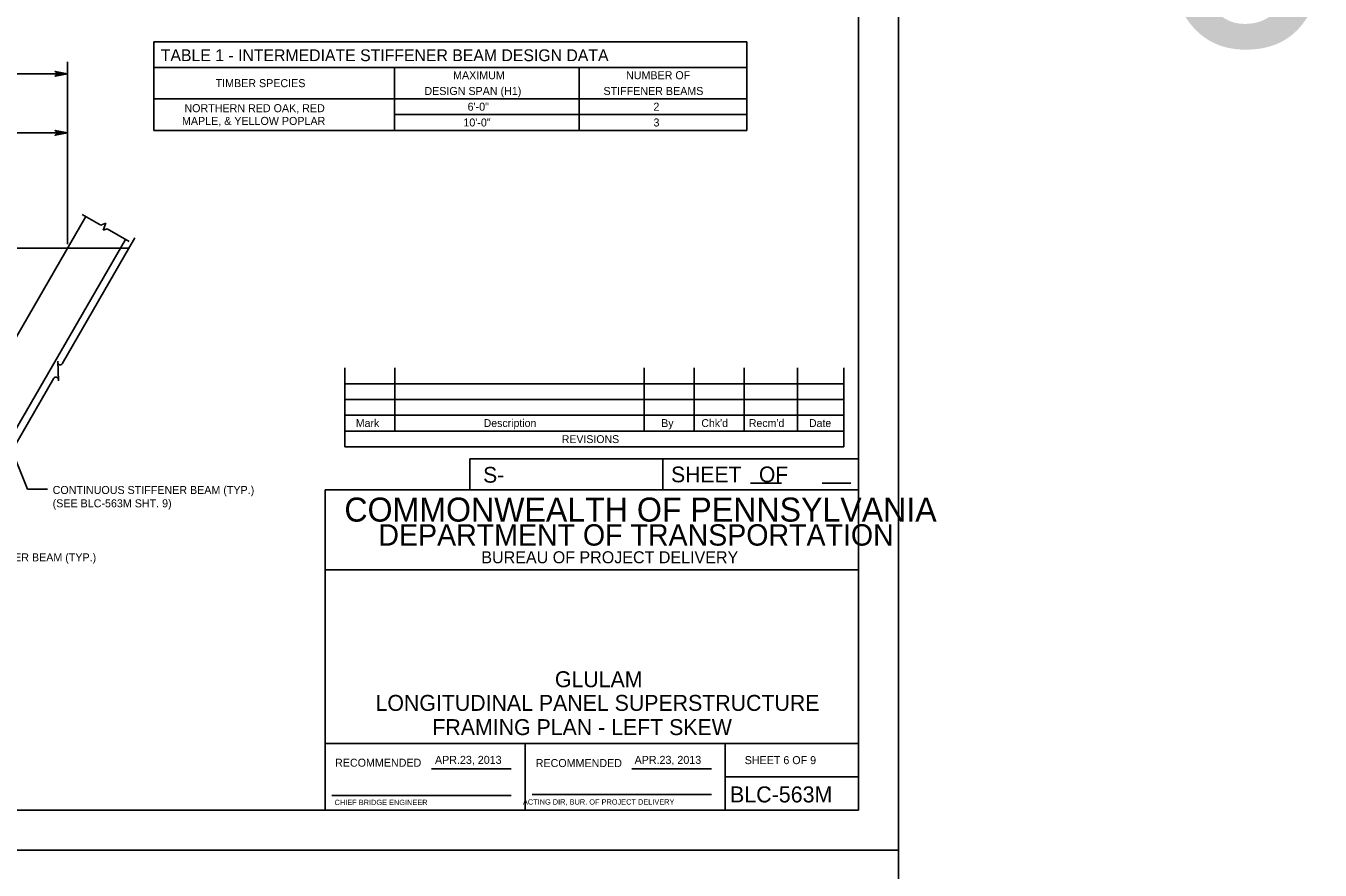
# Model space of a CAD drawing. Extents: x 638268 to 640277, y 295465 to 298435.
# Drawn here: x 639790.3 to 640275.4, y 297834 to 298150.4 of the extents above; entities that cross this region are included whole.
import ezdxf

# ---------------------------------------------------------------- set-up
doc = ezdxf.new("R2010")
doc.units = 0
for name, color, linetype in [('1', 7, 'Continuous'), ('2', 7, 'Continuous'), ('3', 7, 'Continuous'), ('4', 7, 'Continuous'), ('53', 7, 'Continuous'), ('8', 7, 'Continuous'), ('PLT-BNDY', 7, 'Continuous')]:
    doc.layers.add(name, color=color, linetype=linetype)

msp = doc.modelspace()

# ---------------------------------------------------------------- linework, layer by layer
at = {"layer": '2'}
for p, q in [((640102.46, 298420.46), (640102.46, 297856.46)), ((639646.92, 298067.04), (639828.98, 298067.04)), ((639909.92, 298022.15), (639909.92, 297992.62)), ((639928.62, 298022.15), (639928.62, 297998.53)), ((640022.13, 298022.15), (640022.13, 297998.53)), ((640040.83, 298022.15), (640040.83, 297998.53)), ((640059.53, 298022.15), (640059.53, 297998.53)), ((640079.59, 298022.15), (640079.59, 297998.53)), ((640096.94, 298022.15), (640096.94, 297992.62)), ((640096.94, 298016.24), (639909.92, 298016.24)), ((640096.94, 298010.34), (639909.92, 298010.34)), ((640096.94, 298004.43), (639909.92, 298004.43)), ((640096.94, 297998.53), (639909.92, 297998.53)), ((640096.94, 297992.62), (639909.92, 297992.62)), ((640102.46, 297988.11), (639956.78, 297988.11)), ((639956.78, 297988.11), (639956.78, 297976.46)), ((640029.09, 297988.11), (640029.09, 297976.46)), ((640102.46, 297988.11), (640102.46, 297976.46)), ((640061.95, 297979), (640073.6, 297979)), ((640088.83, 297979), (640099.56, 297979)), ((640102.46, 297976.46), (639902.46, 297976.46)), ((639902.46, 297976.46), (639902.46, 297856.46)), ((640102.46, 297976.46), (639956.78, 297976.46)), ((640102.46, 297946.46), (639902.46, 297946.46)), ((640102.46, 297881.46), (639902.46, 297881.46)), ((639977.46, 297856.46), (639977.46, 297881.46)), ((640052.46, 297881.46), (640052.46, 297856.46)), ((639942.42, 297871.96), (639972.19, 297871.96)), ((640017.42, 297871.96), (640047.33, 297871.96)), ((640052.46, 297868.96), (640102.46, 297868.96)), ((639904.96, 297861.96), (639972.19, 297861.96)), ((639980.08, 297862.33), (640047.33, 297862.33)), ((640102.46, 297856.46), (639316.46, 297856.46))]:
    msp.add_line(p, q, dxfattribs=at)
at = {"layer": '3'}
for p, q in [((639812.83, 298078.94), (639754.24, 297977.59)), ((639818.49, 298075.67), (639811.48, 298079.73)), ((639820.29, 298076.41), (639818.49, 298075.67)), ((639819.28, 298073.81), (639820.29, 298076.41)), ((639820.83, 298074.32), (639819.28, 298073.81)), ((639828.99, 298069.6), (639820.83, 298074.32)), ((639769.07, 297969.02), (639827.65, 298070.37)), ((639831.23, 298070.93), (639803.96, 298023.76)), ((639802.25, 298024.67), (639802.52, 298017.4)), ((639800.85, 298018.38), (639776.26, 297975.83))]:
    msp.add_line(p, q, dxfattribs=at)
for centre, start, end in [((639803.18, 298024.22), 179.9708, 329.9708), ((639801.6, 298017.86), 2.1036, 144.6422)]:
    msp.add_arc(centre, 0.909, start, end, dxfattribs=at)
at = {"layer": '4'}
for p, q in [((639805.95, 298068.61), (639805.95, 298136.91)), ((639805.95, 298132.41), (639672.04, 298132.41)), ((639805.95, 298068.61), (639805.95, 298114.76)), ((639764.31, 298110.26), (639805.95, 298110.26)), ((639790.99, 297976.71), (639798.48, 297976.71))]:
    msp.add_line(p, q, dxfattribs=at)
for points in [[(639805.95, 298132.41), (639801.29, 298131.53), (639801.65, 298131.78), (639801.83, 298132.09), (639801.89, 298132.41), (639801.83, 298132.72), (639801.65, 298133.03), (639801.29, 298133.28), (639805.95, 298132.41), (639801.65, 298133.03), (639801.83, 298132.72), (639805.95, 298132.41), (639801.89, 298132.41), (639801.83, 298132.09), (639805.95, 298132.41), (639801.65, 298131.78)], [(639805.95, 298110.26), (639801.29, 298109.38), (639801.65, 298109.63), (639801.83, 298109.94), (639801.89, 298110.26), (639801.83, 298110.57), (639801.65, 298110.88), (639801.29, 298111.13), (639805.95, 298110.26), (639801.65, 298110.88), (639801.83, 298110.57), (639805.95, 298110.26), (639801.89, 298110.26), (639801.83, 298109.94), (639805.95, 298110.26), (639801.65, 298109.63)], [(639783.76, 297994.44), (639790.99, 297976.71)]]:
    msp.add_lwpolyline(points, dxfattribs=at)
for points in [[(639802.95, 298132.91), (639802.95, 298131.91), (639805.95, 298132.41)], [(639802.95, 298110.76), (639802.95, 298109.76), (639805.95, 298110.26)]]:
    msp.add_lwpolyline(points, close=True, dxfattribs=at)
at = {"layer": '8'}
for p, q in [((639838.32, 298144.36), (640060.52, 298144.36)), ((639838.32, 298144.36), (639838.32, 298111.19)), ((640060.52, 298144.36), (640060.52, 298111.19)), ((639838.32, 298134.82), (640060.52, 298134.82)), ((639928.52, 298134.82), (639928.52, 298111.19)), ((639997.74, 298134.82), (639997.74, 298111.19)), ((639838.32, 298123.01), (640060.52, 298123.01)), ((639928.52, 298117.1), (640060.52, 298117.1)), ((639838.32, 298111.19), (640060.52, 298111.19))]:
    msp.add_line(p, q, dxfattribs=at)
at = {"layer": 'PLT-BNDY'}
for points in [[(639276.46, 298435.46), (640117.46, 298435.46), (640117.46, 297841.46), (639276.46, 297841.46)], [(639276.46, 297841.46), (640117.46, 297841.46), (640117.46, 297247.46), (639276.46, 297247.46)]]:
    msp.add_lwpolyline(points, close=True, dxfattribs=at)

# ---------------------------------------------------------------- texts
at = {"layer": '1'}
msp.add_text('SHEET 6 OF 9', height=3, dxfattribs=at).set_placement((640059.77, 297873.68))
at = {"layer": '2'}
for s, height, p in [('Mark', 2.952, (639914.02, 298000.03)), ('Description', 2.9523, (639961.92, 298000.03)), ('By', 2.952, (640028.49, 298000.03)), ("Chk'd", 2.952, (640043.52, 298000.03)), ("Recm'd", 2.953, (640061.33, 298000.03)), ('Date', 2.952, (640083.86, 298000.03)), ('REVISIONS', 2.952, (639991.2, 297994.01)), ('S-', 5.905, (639961.73, 297979.17)), ('COMMONWEALTH OF PENNSYLVANIA', 9, (639909.71, 297964.58)), ('DEPARTMENT OF TRANSPORTATION', 8.0002, (639922.46, 297955.58)), ('BUREAU OF PROJECT DELIVERY', 4.5, (639961.05, 297948.96)), ('APR.23, 2013', 3, (639943.67, 297873.77)), ('APR.23, 2013', 3, (640018.48, 297873.77)), ('BLC-563M', 6, (640054.27, 297859.33)), ('CHIEF BRIDGE ENGINEER', 2.0002, (639906.05, 297858.33)), ('  ACTING DIR, BUR. OF PROJECT DELIVERY', 2.0002, (639975.11, 297858.51))]:
    msp.add_text(s, height=height, dxfattribs=at).set_placement(p)
for s, height, p in [('SHEET   OF', 5.907, (640032.18, 297979.31)), ('RECOMMENDED', 3, (639906.23, 297872.71)), ('RECOMMENDED', 3, (639981.44, 297872.58))]:
    msp.add_text(s, height=height, rotation=360, dxfattribs=at).set_placement(p)
at = {"layer": '4'}
for s, height, p in [('TABLE 1 - INTERMEDIATE STIFFENER BEAM DESIGN DATA', 4.4292, (639840.9, 298137.15)), ('MAXIMUM', 3, (639950.46, 298130.39)), ('NUMBER OF ', 3, (640015.28, 298130.39)), ('TIMBER SPECIES', 3, (639861.45, 298127.41)), ('DESIGN SPAN (H1)', 3, (639939.71, 298124.48)), ('STIFFENER BEAMS', 3, (640006.83, 298124.48)), ('NORTHERN RED OAK, RED', 3, (639849.76, 298118.03)), ('6\'-0"', 3, (639955.9, 298118.58)), ('2', 3, (640025.55, 298118.58)), ('MAPLE, & YELLOW POPLAR', 3, (639848.84, 298113.25)), ('10\'-0"', 3, (639954.32, 298112.67)), ('3', 3, (640025.57, 298112.67)), ('CONTINUOUS STIFFENER BEAM (TYP.)', 3, (639800.37, 297974.93)), ('(SEE BLC-563M SHT. 9)', 3, (639800.37, 297969.93)), ('INTERMEDIATE STIFFENER BEAM (TYP.)', 3, (639738.23, 297949.67)), ('GLULAM', 5.971, (639988.62, 297902.51)), ('LONGITUDINAL PANEL SUPERSTRUCTURE', 5.9714, (639921.39, 297893.65)), ('FRAMING PLAN - LEFT SKEW', 5.9714, (639942.7, 297884.56))]:
    msp.add_text(s, height=height, dxfattribs=at).set_placement(p)
at = {"layer": '53'}
msp.add_text('6', height=93.75, dxfattribs=at).set_placement((640211.23, 298142.79))

doc.saveas('drawing.dxf')
